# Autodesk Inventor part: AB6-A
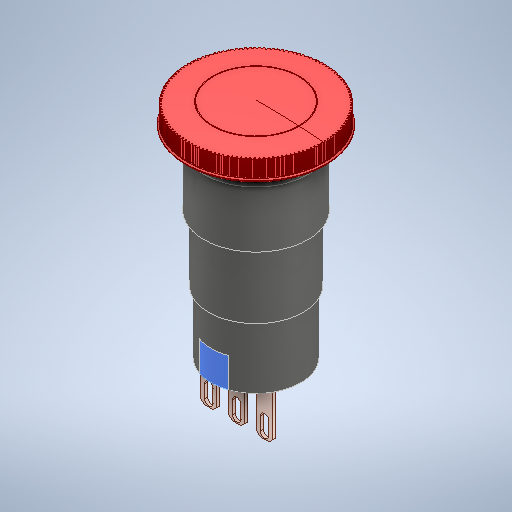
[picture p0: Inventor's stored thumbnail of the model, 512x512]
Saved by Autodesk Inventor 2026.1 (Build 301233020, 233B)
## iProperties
Created: 2026-03
Part Number: AB6-A
Material: Steel
Document SubType Name: Modeling
Designer: hp
Density: 7.85 g/cm^3
Appearance: Default
Title: AB6-A.step
Sending System: Autodesk Translation Framework v14.24.0.0
Preprocessor: ST-DEVELOPER v20.1
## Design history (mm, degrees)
feature "Body1"
feature "Body2"
feature "Body3"
feature "Body6"
feature "Body7"
feature "Body8"
feature "Body5"
feature "Body9"
body "Solid1"
body "Solid2"
body "Solid3"
body "Solid4"
body "Solid5"
body "Solid6"
body "Solid7"
body "Solid8"
